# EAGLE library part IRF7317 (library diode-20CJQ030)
International Rectifier's IRF7317 HEXFET® Power MOSFET Description: Fifth Generation HEXFETs from International Rectifier utilize advanced processing techniques to achieve extremely low on-resistance per silicon area. This benefit, combined with the fast switching speed and ruggedized device design that HEXFET Power MOSFETs are well known for, provides the designer with an extremely efficient and reliable device for use in a wide variety of applications. The SO-8 has been modified through a customized leadframe for enhanced thermal characteristics and multiple-die capability making it ideal in a variety of power applications. With these improvements, multiple devices can be used in an application with dramatically reduced board space. The package is designed for vapor phase, infra red, or wave soldering techniques. Features: Generation V Technology Ultra Low On-Resistance Dual N and P Channel MOSFET Surface Mount Fully Avalanche Rated Please send any comments to: messi@users.sourceforge.net
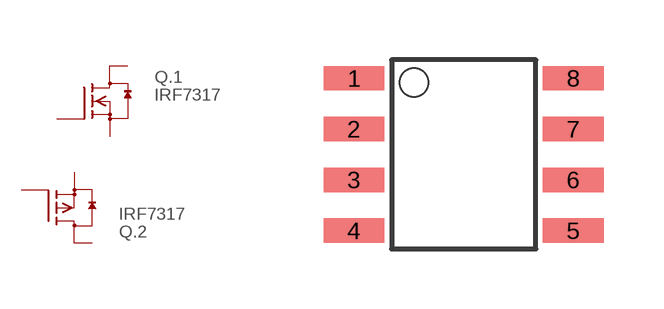
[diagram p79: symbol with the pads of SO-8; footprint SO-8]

Designator prefix Q; gates .1=IGFET-4-N-CH .2=IGFET-4-P-CH

## IRF7317  [SO-8]
1  .1:S  pas
2  .1:G  pas
3  .2:S  pas
4  .2:G  pas
5  .2:D  pas
6  .2:D  pas
7  .1:D  pas
8  .1:D  pas

## Footprint SO-8 (pad centres in mm)
small outline
smd 1.524 x 0.61: 1 -2.743,1.27; 2 -2.743,0; 3 -2.743,-1.27; 4 -2.743,-2.54; 5 2.743,-2.54; 6 2.743,-1.27; 7 2.743,0; 8 2.743,1.27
